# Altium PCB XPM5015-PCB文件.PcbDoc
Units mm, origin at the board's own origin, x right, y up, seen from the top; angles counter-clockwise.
Board outline 44.07 x 16 mm, 2 copper layers (Top Layer, Bottom Layer); 14 components, 8 nets, 47 pads, 23 vias.
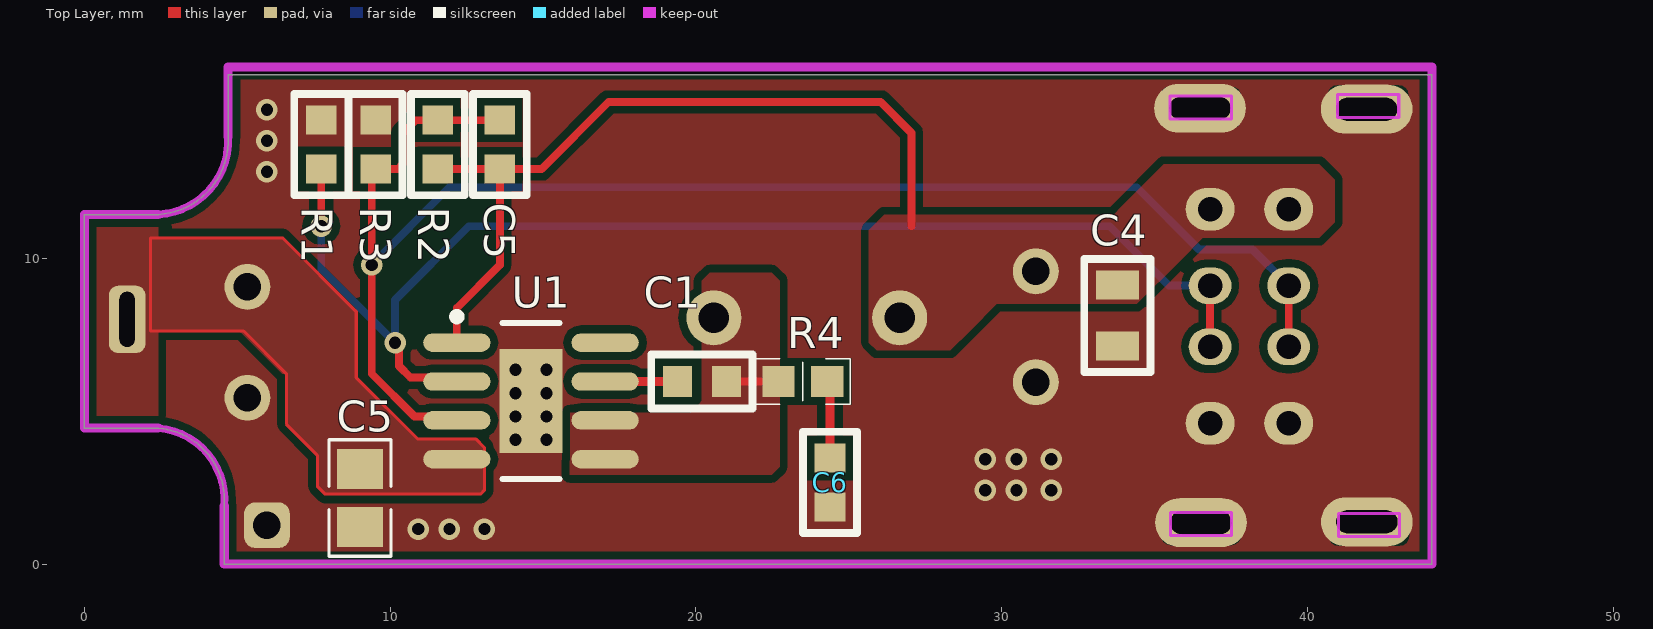
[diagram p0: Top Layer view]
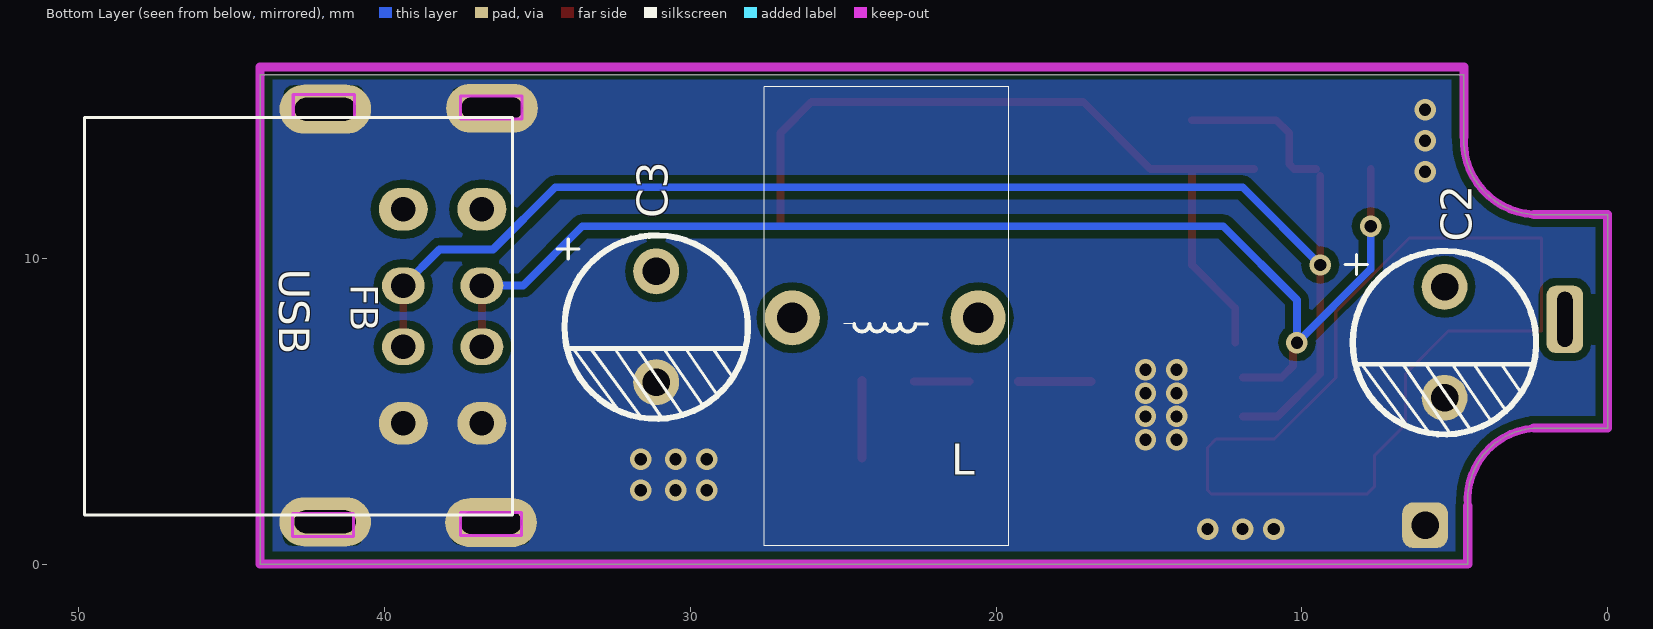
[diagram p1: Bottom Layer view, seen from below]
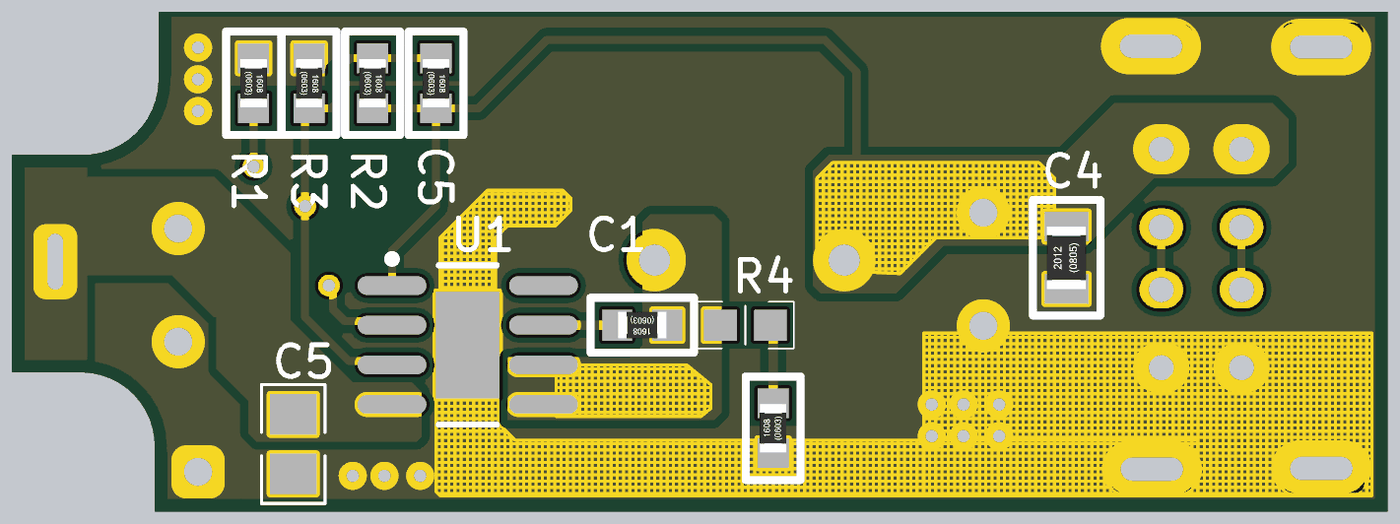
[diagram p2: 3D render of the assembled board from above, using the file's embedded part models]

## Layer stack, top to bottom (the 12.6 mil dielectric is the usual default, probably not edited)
Top Layer: signal copper 0.0356
Dielectric: dielectric 0.32, FR-4, Dk 4.8
Bottom Layer: signal copper 0.0356

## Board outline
0,4.445 0,11.43 2.413,11.43 ccw(c2.286,13.843) 4.699,13.97 4.699,16 44.069,16 44.069,0 4.572,0 4.572,1.905 ccw(c2.222,2.095) 2.413,4.445

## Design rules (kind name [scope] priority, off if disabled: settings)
Clearance [All] p1: gap=0.254
PolygonConnect [All] p1: connectstyle=Direct reliefconductorwidth=0.254 reliefentries=4 polygonreliefangle="90 Angle" airgapwidth=0.254
RoutingVias [All] p1: holewidth=0.711 width=1.27 viastyle="Through Hole" minholewidth=0.711 minwidth=1.27 maxholewidth=0.711 maxwidth=1.27
SolderMaskExpansion [All] p1: expansion=0.102
Width [All] p1: maxlimit=0.5 minlimit=0.1 preferedwidth=0.3
28 further rules are at their usual default settings.

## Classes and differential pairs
component class yx1106: C2 C3 C5 C6 L R1 R2 R3 U1

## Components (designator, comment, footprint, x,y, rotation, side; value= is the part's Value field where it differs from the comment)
C1 "0.1uF" 0603 20.193,5.969 r180 top
C2 "100uF/35V" 100uF/25V 5.334,7.239 r90 bottom
C3 "220uF/25V" 100uF/25V 31.115,7.747 r90 bottom
C4 "mycap" 0805 33.782,8.128 r90 top
C5 "100pF" 0603 13.589,13.716 r270 top
C5 "2.2uF/35V" 0805-1 9.017,2.159 r270 top
C6 "" 0603 24.384,2.667 r90 top (schematic designator C?)
L "33uH" 绕线电感 21.463,8.128 r0 bottom
R1 "RES" 0603 7.747,13.716 r270 top
R2 "100K" 0603 11.557,13.716 r270 top
R3 "56K" 0603 9.525,13.716 r270 top
R4 "RES" RES0603 23.495,5.969 r0 top (schematic designator R?)
U1 "XPM5015" ESOP-8 14.605,5.334 r0 top (schematic designator *)
USB "" "USB DOBULE" 35.814,14.605 r0 bottom

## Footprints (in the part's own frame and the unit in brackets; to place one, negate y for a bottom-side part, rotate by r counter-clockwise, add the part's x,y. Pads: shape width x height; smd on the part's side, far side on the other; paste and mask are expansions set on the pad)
100uF/25V [mm]
  round 1.5 hole 0.9: 1(1.825,0) 2(-1.8,0)
  silkscreen extent -3,-3 3,3.25
0603 [mm] "SMD, 0603"
  rect 0.95x1 smd: 1(-0.8,0) 2(0.8,0)
  silkscreen extent -1.66,-0.88 1.66,0.88, body extent -0.77,-0.43 0.77,0.43, height 0.45
0805 [mm] "SMD, 0805"
  rect 0.95x1.4 smd: 1(-1,0) 2(1,0)
  silkscreen extent -1.85,-1.08 1.85,1.08, body extent -1,-0.62 1,0.63, height 0.45
0805-1 [mm] "贴片带丝印"
  rect 1.3x1.5 smd: 1(-0.95,0) 2(0.95,0)
  silkscreen extent -1.91,-1.02 1.91,1.02, body extent -1.14,-0.51 1.14,0.51, height 1
ESOP-8 [mm] "SOP, 8-Leads, Body 4.90x3.90mm, Pitch 1.27mm, Thermal Pad 3.41.2x2.05.2mm, IPC Medium Density"
  oval 2.2x0.6 smd: 1(-2.425,1.905) 2(-2.425,0.635) 3(-2.425,-0.635) 4(-2.425,-1.905) 5(2.425,-1.905) 6(2.425,-0.635) 7(2.425,0.635) 8(2.425,1.905)
  rect 2.05x3.41 smd: 9(0,0)
  silkscreen extent -2.55,-2.55 0.93,2.88, body extent -2,-2.55 2,2.55, height 2.65
RES0603 [mm] "0603贴片电阻"
  rect 1.05x1 smd: 1(-0.8,0) 2(0.8,0)
  silkscreen extent -1.55,-0.75 1.55,0.75
"USB DOBULE" [mm]
  oval 1.6x1.4 hole 0.8: 1(1,10) 1(3.57,10) 4(1,3) 4(3.57,3)
  oval 1.4x1.2 hole 0.8: 2(1,7.5) 2(3.57,7.5) 3(1,5.5) 3(3.57,5.5)
  oval 3x1.6 hole 0.75 slot 2 at 0 deg: ""(0.67,-0.3) ""(0.7,13.25) ""(6.12,-0.271) ""(6.125,13.225)
  Keep-Out Layer lines w0.1: -0.305,0.054 -0.305,-0.696 1.695,-0.696 1.695,0.054 -0.305,0.054 ; -0.3,13.675 -0.3,12.925 1.7,12.925 1.7,13.675 -0.3,13.675 ; 5.17,0.004 7.17,0.004 7.17,-0.746 5.17,-0.746 5.17,0.004 ; 5.2,13.7 7.2,13.7 7.2,12.95 5.2,12.95 5.2,13.7
  silkscreen extent 0,0 14,13
绕线电感 [mm]
  round 1.8 hole 1: 1(-0.875,0.075) 2(5.2,0.075)
  silkscreen extent -1.87,-7.48 6.13,7.52

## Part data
C1 C5 C6: library part mycap
C2 C3: library part "cap pol"
L: library part insductor
R2 R3: library part RES
U1: library part YX1105

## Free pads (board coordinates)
  rrect50% 1.2x2.2 hole 0.5 slot 1.8 at 90 deg: 0(1.397,8.001)
  rrect50% 1.5x1.5 hole 0.9: 1(5.969,1.27)

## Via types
v1: diameter 0.7, hole 0.4, Top Layer to Bottom Layer, 23 vias

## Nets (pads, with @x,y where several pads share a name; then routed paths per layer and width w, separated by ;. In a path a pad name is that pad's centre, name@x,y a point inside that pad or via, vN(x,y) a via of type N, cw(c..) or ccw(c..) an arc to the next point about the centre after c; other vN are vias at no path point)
12V~24V: C2.1 C5.1@9.017,3.109 pad.0 U1.4 | length 34.2
  Top Layer w0.1: 2.159,7.62 2.159,10.668 6.477,10.668 8.89,8.255 8.89,6.096 10.891,4.095 12.796,4.095 13.081,3.81 13.081,2.413 12.954,2.286 7.874,2.286 7.62,2.54 7.62,3.556 6.604,4.572 6.604,6.223 5.207,7.62 2.159,7.62
COMP: R1.2 U1.2 USB.2@36.814,7.105 USB.3@36.814,9.105 | length 41.1
  Top Layer w0.254: v1(7.747,11.049) R1.2 ; v1(10.16,7.239) 10.287,7.112 10.287,6.477 10.668,6.096 U1.2@11.926,6.096 ; USB.2@36.814,6.897 36.814,7.105 USB.3@36.814,8.897
  Bottom Layer w0.254: v1(7.747,11.049) 7.747,9.652 v1(10.16,7.239) 10.16,8.636 12.573,11.049 33.528,11.049 35.472,9.105 USB.3@36.814,9.105
GND: C2.2 C3.2 C4.1 C5.2@9.017,1.209 C6.1 pad.1 R1.1 R3.1 U1.9 USB. USB.1
  other v1: 10.922,1.143 11.938,1.143 13.081,1.143 29.464,2.413 30.48,2.413 31.623,2.413 29.464,3.429 30.48,3.429 31.623,3.429 14.097,4.064 15.113,4.064 14.097,4.826 15.113,4.826 14.097,5.588 15.113,5.588 14.097,6.35 15.113,6.35 5.969,12.827 5.969,13.843 5.969,14.859
Net*_1: C3.1 C4.2 C5.2@13.589,12.916 L.2 R2.2 U1.1 USB.4 | length 26.1
  Top Layer w0.254: R2.2 C5.2@13.589,12.916 ; U1.1 12.18,8.37 13.589,9.779 C5.2@13.589,12.916 ; 27.051,11.049 27.051,14.097 26.035,15.113 17.145,15.113 14.948,12.916 C5.2@13.589,12.916
Net*_3: C5.1@13.589,14.516 R2.1 R3.2 U1.3 USB.2@39.384,7.105 USB.3@39.384,9.105 | length 49.3
  Top Layer w0.254: R3.2@9.398,12.7 v1(9.398,9.779) 9.398,6.223 10.795,4.826 U1.3@11.926,4.826 ; R3.2 10.249,12.916 10.414,13.081 10.414,14.097 10.833,14.516 R2.1 C5.1@13.589,14.516 ; USB.2@39.384,6.897 39.384,7.105 USB.3@39.384,8.897
  Bottom Layer w0.254: v1(9.398,9.779) 11.938,12.319 34.417,12.319 36.449,10.287 38.202,10.287 USB.3@39.384,9.105
Net*_5: C1.1 L.1 R4.1 U1.5 U1.6 | length 1.8
  Top Layer w0.254: C1.1@20.866,5.969 R4.1
Net*_7: C1.2 U1.7 | length 2.4
  Top Layer w0.3: U1.7@16.903,5.969 C1.2@19.266,5.969
NetC?_2: C6.2 R4.2 | length 2.5
  Top Layer w0.3: C6.2 R4.2@24.384,6.007
pads on no net: U1.8

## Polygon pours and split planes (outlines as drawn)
12V~24V on Top Layer "Bottom Layer" (solid, remove dead copper, pour order 38): 2.413,11.43 0,11.43 0,4.445 2.413,4.445
12V~24V on Top Layer "Bottom Layer" (solid, remove dead copper, pour order 42): 2.413,7.62 5.08,7.62 6.477,6.223 6.604,6.223 6.604,4.572 7.62,3.556 7.62,2.54 7.874,2.286 12.954,2.286 13.081,2.413 13.081,3.81 12.796,4.095 10.891,4.095 8.89,6.096 8.89,8.255 6.477,10.668 2.413,10.668
Net*_5 on Top Layer "Bottom Layer" (solid, remove dead copper, pour order 44): 15.875,4.953 19.558,4.953 19.812,4.953 20.193,5.334 20.193,8.636 20.193,9.271 20.447,9.525 21.844,9.525 22.479,9.525 22.606,9.398 22.733,9.271 22.733,6.985 22.733,3.175 22.479,2.921 15.875,2.921
Net*_1 on Top Layer "Bottom Layer" (solid, remove dead copper, pour order 50): 25.654,8.636 25.654,7.239 25.908,6.985 28.194,6.985 28.321,6.985 28.956,7.62 29.845,8.509 32.639,8.509 34.417,8.509 35.814,9.906 36.576,10.668 40.132,10.668 40.386,10.668 40.894,11.176 40.894,12.573 40.386,13.081 35.941,13.081 35.306,13.081 33.909,11.684 33.655,11.43 26.543,11.43 26.162,11.43 25.654,10.922
GND on Top Layer "Bottom Layer" (solid, remove dead copper, pour order 58): 0,16.51 0,0.127 -0.127,0 44.069,0 44.069,16
GND on Bottom Layer "Bottom Layer" (solid, remove dead copper, pour order 56): 0,0 0,16.51 44.196,16.51 44.323,16.383 44.323,0
GND on Top Solder "Bottom Layer" (hatched 90Degree grid 0.2 track 0.1, remove dead copper): 13.589,5.588 13.589,0.635 13.716,0.508 37.973,0.508 37.973,1.016 37.973,2.286 16.129,2.286 15.621,2.794 15.621,5.588
GND on Top Solder "Bottom Layer" (hatched 90Degree grid 0.2 track 0.1, remove dead copper): 35.119,5.715 29.21,5.715 29.21,0.508 43.561,0.508 43.561,5.715
Net*_5 on Top Solder "Bottom Layer" (hatched 90Degree grid 0.2 track 0.1, remove dead copper): 17.434,4.572 17.589,4.699 19.601,4.699 21.613,4.699 21.923,4.445 22.387,4.064 22.387,3.556 22.387,3.302 22.078,3.048 17.434,3.048
GND on Top Solder "Bottom Layer" (hatched 90Degree grid 0.2 track 0.1, remove dead copper): 13.716,6.731 13.716,8.763 14.351,9.398 15.24,10.287 16.002,10.287 17.653,10.287 17.78,10.16 17.907,10.033 17.907,9.652 17.653,9.398 17.399,9.144 16.002,9.144 15.875,9.144 15.494,8.763 15.494,6.731
Net*_1 on Top Solder "Bottom Layer" (hatched 90Degree grid 0.2 track 0.1, remove dead copper): 25.781,7.747 25.781,10.541 25.781,10.668 26.162,11.049 26.289,11.176 29.972,11.176 32.893,11.176 33.401,10.668 33.401,10.541 33.401,9.017 33.147,8.763 29.972,8.763 29.591,8.763 28.448,7.62

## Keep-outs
Keep-Out Layer:
  lines w0.254: 2.413,4.445 cw(c2.222,2.095) 4.572,1.905 ; 2.413,11.43 ccw(c2.286,13.843) 4.699,13.97
  lines w0.3: 2.413,4.445 0,4.445 0,11.43 2.413,11.43 ; 4.572,1.905 4.572,0 44.069,0 44.069,16.256 4.699,16.256 4.699,13.97

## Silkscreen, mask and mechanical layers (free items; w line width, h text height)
Bottom Overlay:
  text "FB" at 41.402,9.144 h1.52 r90

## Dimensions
44.069,16.256 to 44.069,0 on Keep-Out Layer
44.069,0 to 0,4.445 on Keep-Out Layer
